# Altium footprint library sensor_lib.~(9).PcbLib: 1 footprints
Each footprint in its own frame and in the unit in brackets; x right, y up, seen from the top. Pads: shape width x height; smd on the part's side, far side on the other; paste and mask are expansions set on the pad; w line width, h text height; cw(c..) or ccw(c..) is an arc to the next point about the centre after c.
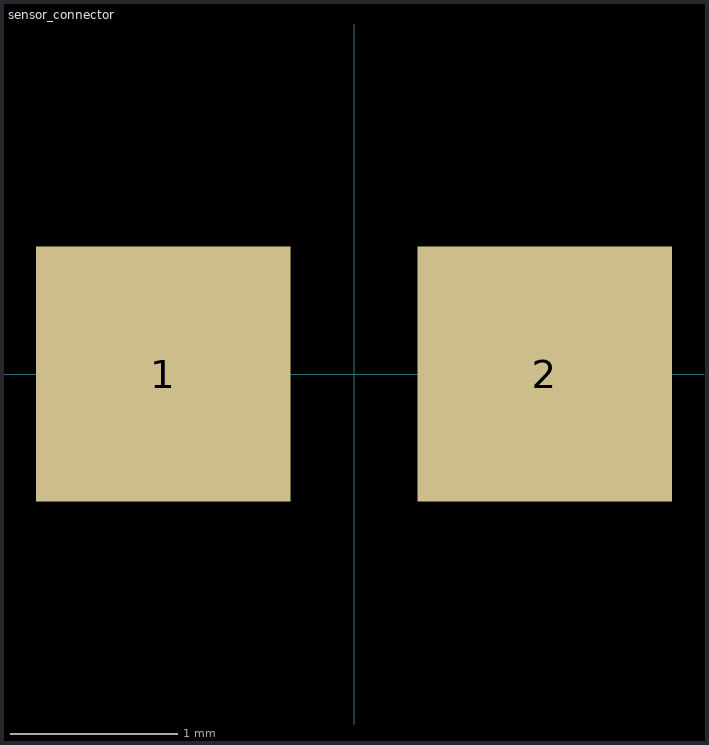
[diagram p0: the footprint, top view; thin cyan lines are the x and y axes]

## sensor_connector [mil]
pads (2):
  rect 60x60 smd: 1(-45,0) 2(45,0)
